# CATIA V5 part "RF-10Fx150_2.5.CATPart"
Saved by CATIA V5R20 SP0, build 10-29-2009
Part number: _RF-10Fx150/2.5
Definition: NONE
Nomenclature: _RF-10Fx150/2.5
Source: Unknown
Description: PART-_RF-10Fx150/2.5-DESC
Bounding box of the stored display mesh (mm): x -150 to 22.5, y -5.65 to 5.65, z -5.65 to 5.65
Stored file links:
  C:\Users\Utente\Desktop\IO LAVORO\3D X SITO CF\X SITO\PLASTICA\RFF\RF-10Fx150_2.5.CATPart

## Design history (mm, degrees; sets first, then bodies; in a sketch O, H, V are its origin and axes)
Body1 "_RF-10Fx150/2.5" (main body)
  Solid1: solid without history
